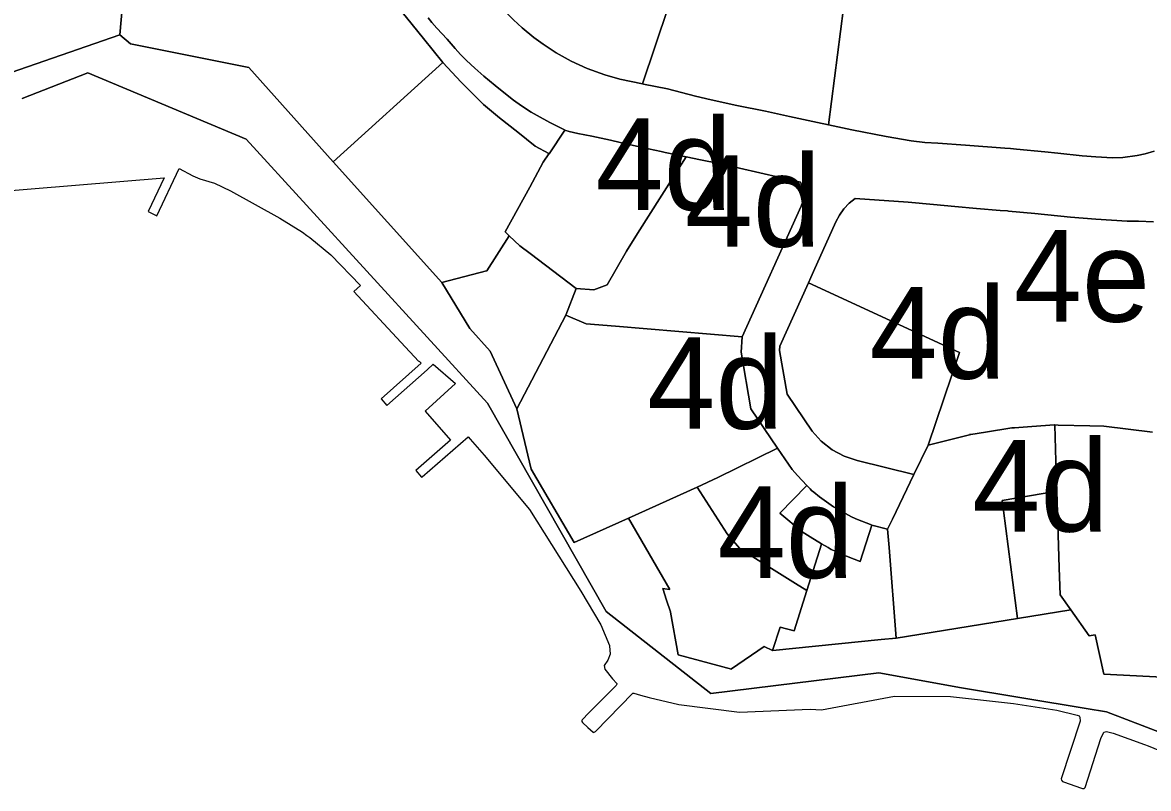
# Model space of a CAD drawing. Extents: x 598968 to 613553, y 4409678 to 4430833.
# Drawn here: x 608951 to 609098.4, y 4416657.6 to 4416758 of the extents above; entities that cross this region are included whole.
import ezdxf

# ---------------------------------------------------------------- set-up
doc = ezdxf.new("R2010")
doc.units = 0
for name, color, linetype in [('1', 7, 'Continuous'), ('4d. Sector de consolidació - ANNEX III A', 7, 'Continuous'), ('4e. Sector de consolidació - ANNEX III A', 7, 'Continuous')]:
    doc.layers.add(name, color=color, linetype=linetype)

msp = doc.modelspace()

# ---------------------------------------------------------------- linework, layer by layer
at = {"layer": '1'}
for points in [[(608987.0877, 4416776.1416), (609003.4782, 4416755.8932), (609006.0154, 4416752.7588), (609008.397, 4416750.1506), (609011.328, 4416747.2255), (609013.4226, 4416745.4815), (609015.8455, 4416743.5998), (609018.1041, 4416741.787), (609019.8769, 4416740.8037), (609019.9102, 4416740.7852), (609021.9971, 4416743.894), (609021.945, 4416743.9178), (609020.0295, 4416744.875), (609018.3446, 4416745.7945), (609017.5768, 4416746.2442), (609016.2868, 4416747.0752), (609015.2545, 4416747.8133), (609014.2052, 4416748.6265), (609012.8624, 4416749.7131), (609011.3621, 4416750.9714), (609010.1811, 4416752.0005), (609009.0988, 4416753.0034), (609008.3312, 4416753.7846), (609007.6371, 4416754.5791), (609006.5937, 4416755.7997), (609005.2224, 4416757.2264), (609004.5585, 4416757.9704), (609004.0997, 4416758.5969)], [(609060.0592, 4416772.136), (609056.5294, 4416744.5677), (609056.5287, 4416744.5623), (609059.5763, 4416743.9307), (609064.0504, 4416743.0457), (609067.3301, 4416742.4837), (609069.136, 4416742.2794), (609070.8092, 4416742.1551), (609074.4638, 4416741.8916), (609079.5883, 4416741.5384), (609080.3625, 4416741.4743), (609081.1235, 4416741.3972), (609084.8211, 4416741.0164), (609086.5239, 4416740.8418), (609089.7094, 4416740.5159), (609091.5331, 4416740.3631), (609093.6845, 4416740.2563), (609095.0525, 4416740.2923), (609096.9507, 4416740.5399), (609097.9963, 4416740.7699), (609099.1764, 4416741.1323)], [(609004.0997, 4416758.5969), (609004.5585, 4416757.9704), (609005.2224, 4416757.2264), (609006.5937, 4416755.7997), (609007.6371, 4416754.5791), (609008.3312, 4416753.7846), (609009.0988, 4416753.0034), (609010.1811, 4416752.0005), (609011.3621, 4416750.9714), (609012.8624, 4416749.7131), (609014.2052, 4416748.6265), (609015.2545, 4416747.8133), (609016.2868, 4416747.0752), (609017.5768, 4416746.2442), (609018.3446, 4416745.7945), (609020.0295, 4416744.875), (609021.945, 4416743.9178), (609021.9971, 4416743.894), (609022.5575, 4416743.6945), (609023.6832, 4416743.4548), (609025.525, 4416743.1017), (609027.9815, 4416742.5463), (609029.2108, 4416742.2692), (609032.9329, 4416741.4381), (609034.5963, 4416741.0709), (609035.101, 4416740.9643), (609037.87, 4416740.3973), (609039.7574, 4416740.0094), (609042.1979, 4416739.4918), (609052.8646, 4416737.0656), (609053.0938, 4416736.4551), (609053.2159, 4416735.8146), (609053.2272, 4416735.1627), (609053.1276, 4416734.5183), (609052.9198, 4416733.9002), (609045.2239, 4416716.8026), (609045.0867, 4416714.7828), (609046.3281, 4416707.381), (609049.8464, 4416702.2208), (609051.7312, 4416699.4396), (609052.4592, 4416698.6219), (609053.6779, 4416697.3359), (609054.0958, 4416696.8949), (609054.3043, 4416696.675), (609054.6107, 4416696.4424), (609055.3228, 4416695.8164), (609057.1475, 4416694.5167), (609059.506, 4416693.2163), (609059.6005, 4416693.1642), (609060.3276, 4416692.8771), (609062.006, 4416692.2144), (609062.206, 4416692.1354), (609064.2562, 4416691.5819), (609064.9022, 4416692.9286), (609067.6919, 4416698.7433), (609060.2533, 4416700.5877), (609058.5552, 4416701.1622), (609056.9792, 4416702.0165), (609055.5712, 4416703.1262), (609054.372, 4416704.4588), (609051.0777, 4416709.2906), (609050.1149, 4416715.0303), (609050.1515, 4416715.5686), (609053.8948, 4416723.885), (609054.2012, 4416724.5657), (609054.5515, 4416725.344), (609057.4791, 4416731.8482), (609057.9344, 4416732.7525), (609058.5173, 4416733.5805), (609059.2152, 4416734.3144), (609060.0129, 4416734.938), (609066.928, 4416734.4492), (609070.2692, 4416734.1299), (609073.0466, 4416733.8661), (609075.8834, 4416733.6256), (609078.9895, 4416733.373), (609079.9699, 4416733.2884), (609080.0752, 4416733.2796), (609083.5204, 4416732.9464), (609088.219, 4416732.48), (609091.5363, 4416732.214), (609095.633, 4416731.9749), (609097.0929, 4416731.9379), (609099.0532, 4416731.8883)], [(609099.1764, 4416741.1323), (609097.9963, 4416740.7699), (609096.9507, 4416740.5399), (609095.0525, 4416740.2923), (609093.6845, 4416740.2563), (609091.5331, 4416740.3631), (609089.7094, 4416740.5159), (609086.5239, 4416740.8418), (609084.8211, 4416741.0164), (609081.1235, 4416741.3972), (609080.3625, 4416741.4743), (609079.5883, 4416741.5384), (609074.4638, 4416741.8916), (609070.8092, 4416742.1551), (609069.136, 4416742.2794), (609067.3301, 4416742.4837), (609064.0504, 4416743.0457), (609059.5763, 4416743.9307), (609056.5287, 4416744.5623), (609055.079, 4416744.8708), (609051.3947, 4416745.6653), (609048.2395, 4416746.3451), (609044.5273, 4416747.1241), (609041.1325, 4416747.838), (609039.0863, 4416748.3369), (609035.4392, 4416749.2726), (609032.2943, 4416749.9113), (609032.1364, 4416749.9379), (609029.1931, 4416750.5426), (609027.1985, 4416751.1124), (609024.9086, 4416751.9602), (609022.7972, 4416752.9261), (609020.8487, 4416754.0143), (609019.125, 4416755.1325), (609017.9389, 4416756.0081), (609016.413, 4416757.2806), (609015.2628, 4416758.3509)], [(609100.2514, 4416672.2155), (609092.5832, 4416672.5994), (609091.4176, 4416677.7434), (609090.6308, 4416677.6353), (609088.2429, 4416681.0208), (609081.2483, 4416679.8886), (609065.3862, 4416677.3213), (609063.4291, 4416677.1277), (609049.1998, 4416675.7197), (609049.1955, 4416675.7212), (609048.0996, 4416676.2155), (609043.7951, 4416673.2812), (609043.7927, 4416673.2795), (609036.8413, 4416675.148), (609035.8312, 4416680.7472), (609035.8296, 4416680.7529), (609035.3159, 4416682.312), (609034.8144, 4416683.8355), (609035.0867, 4416683.8029), (609035.7392, 4416683.6936), (609030.298, 4416693.0468), (609023.2232, 4416689.845), (609017.5907, 4416699.45), (609015.7009, 4416707.372), (609012.182, 4416714.9272), (609009.5399, 4416717.894), (609005.856, 4416723.919), (609005.8631, 4416723.9218), (608991.6521, 4416739.7249), (608980.5997, 4416752.0903), (608965.091, 4416755.1885), (608963.7088, 4416756.3476), (608948.3247, 4416751.0557)], [(608950.9096, 4416748.0147), (608959.5132, 4416751.3932), (608980.2407, 4416742.6806), (609011.8707, 4416708.1096), (609027.3949, 4416680.8073), (609041.0946, 4416670.0876), (609063.0829, 4416672.7865), (609066.7132, 4416672.1246), (609073.6662, 4416670.8568), (609073.6719, 4416670.8559), (609090.2482, 4416668.1064), (609092.9199, 4416667.6633), (609117.6195, 4416658.1771)], [(609117.6195, 4416658.1771), (609092.9199, 4416667.6633), (609090.2482, 4416668.1064), (609073.6719, 4416670.8559), (609073.6662, 4416670.8568), (609066.7132, 4416672.1246), (609063.0829, 4416672.7865), (609041.0946, 4416670.0876), (609027.3949, 4416680.8073), (609011.8707, 4416708.1096), (608980.2407, 4416742.6806), (608959.5132, 4416751.3932), (608950.9096, 4416748.0147)], [(608946.2527, 4416735.7078), (608969.4922, 4416737.6286), (608967.4022, 4416733.2086), (608967.7454, 4416733.0473), (608968.5722, 4416732.6586), (608971.4921, 4416738.8386), (608973.2618, 4416737.9081), (608974.192, 4416737.4987), (608976.122, 4416736.9188), (608978.202, 4416735.9289), (608984.6718, 4416732.3292), (608987.6318, 4416730.4994), (608988.2052, 4416730.0932), (608988.5918, 4416729.8194), (608991.3318, 4416727.5396), (608995.2216, 4416723.5298), (608994.3517, 4416722.7198), (609000.5123, 4416716.0811), (609002.8516, 4416713.5604), (609002.925, 4416713.6247), (609003.1808, 4416713.3492), (608997.9079, 4416708.6911), (608998.6739, 4416707.8231), (609003.9468, 4416712.4812), (609004.7272, 4416713.2172), (609007.6714, 4416710.6906), (609003.6916, 4416707.0506), (609007.0015, 4416703.2408), (609002.4616, 4416699.2907), (609003.2316, 4416698.4008), (609003.3151, 4416698.4731), (609009.3414, 4416703.6908), (609009.5843, 4416703.4118), (609011.4214, 4416701.301), (609017.3414, 4416694.1614), (609024.0912, 4416683.4718), (609026.6912, 4416679.0521), (609027.8116, 4416676.3789), (609027.8312, 4416676.3322), (609027.9212, 4416675.2022), (609027.6012, 4416674.4222), (609027.1412, 4416673.7222), (609027.2312, 4416673.2522), (609028.2312, 4416672.0023), (609028.8012, 4416671.3624), (609028.7912, 4416671.2924), (609028.7612, 4416671.2224), (609028.7012, 4416671.1024), (609025.9213, 4416668.3423), (609025.7726, 4416668.1892), (609025.1286, 4416667.5258), (609024.2514, 4416666.6223), (609024.2114, 4416666.5123), (609024.2114, 4416666.4123), (609024.3114, 4416666.2623), (609025.0033, 4416665.6314), (609025.6713, 4416665.0224), (609025.7713, 4416664.9824), (609025.8083, 4416664.9994), (609026.0113, 4416665.0924), (609030.9012, 4416670.0924), (609031.0212, 4416670.1324), (609031.8712, 4416669.8625), (609033.0311, 4416669.5326), (609036.921, 4416668.6127), (609044.8708, 4416667.613), (609054.0906, 4416668.0133), (609055.6006, 4416667.9434), (609065.1504, 4416669.7236), (609065.1607, 4416669.7235), (609072.4702, 4416669.6639), (609080.75, 4416668.7442), (609086.3999, 4416667.8844), (609089.0898, 4416667.2446), (609089.3298, 4416667.1246), (609089.3714, 4416667.0552), (609089.4198, 4416666.9746), (609089.4201, 4416666.9686), (609089.4498, 4416666.4446), (609086.99, 4416658.8947), (609087.02, 4416658.7247), (609087.17, 4416658.5547), (609087.4371, 4416658.4565), (609089.5099, 4416657.6948), (609089.7899, 4416657.6248), (609090.0099, 4416657.6448), (609090.1099, 4416657.7648), (609092.1698, 4416664.1547), (609092.5598, 4416665.0047), (609092.8998, 4416665.0847), (609093.8098, 4416664.8848), (609097.8897, 4416663.405), (609098.3796, 4416663.235), (609104.0996, 4416660.8352)]]:
    msp.add_lwpolyline(points, dxfattribs=at)
for points in [[(609019.9102, 4416740.7852), (609019.8769, 4416740.8037), (609018.1041, 4416741.787), (609015.8455, 4416743.5998), (609013.4226, 4416745.4815), (609011.328, 4416747.2255), (609008.397, 4416750.1506), (609006.0154, 4416752.7588), (608991.6521, 4416739.7249), (609005.8631, 4416723.9218), (609011.7447, 4416725.4549), (609011.7518, 4416725.4574), (609014.6929, 4416730.0384), (609014.6968, 4416730.0445), (609014.1486, 4416730.5608), (609017.3955, 4416736.4272), (609019.1395, 4416739.6686), (609019.8997, 4416740.7696)], [(609023.4587, 4416723.143), (609017.4252, 4416727.7126), (609016.0943, 4416728.7286), (609014.6968, 4416730.0445), (609014.6929, 4416730.0384), (609011.7518, 4416725.4574), (609011.7447, 4416725.4549), (609005.8631, 4416723.9218), (609005.856, 4416723.919), (609009.5399, 4416717.894), (609012.182, 4416714.9272), (609015.7009, 4416707.372), (609022.1296, 4416719.6574)], [(609053.6779, 4416697.3359), (609052.4592, 4416698.6219), (609051.7312, 4416699.4396), (609049.8464, 4416702.2208), (609049.8394, 4416702.2176), (609042.0379, 4416698.3597), (609039.3057, 4416697.1233), (609043.2608, 4416691.0109), (609044.852, 4416689.1018), (609044.8662, 4416689.0849), (609052.1805, 4416684.466), (609053.6866, 4416683.5509), (609055.6006, 4416689.6141), (609055.5931, 4416689.6191), (609055.615, 4416689.6889), (609054.0936, 4416690.605), (609053.0784, 4416691.2725), (609050.1529, 4416693.7137), (609053.6396, 4416697.296)], [(609062.206, 4416692.1354), (609062.006, 4416692.2144), (609060.3276, 4416692.8771), (609059.6005, 4416693.1642), (609059.506, 4416693.2163), (609057.1475, 4416694.5167), (609055.3228, 4416695.8164), (609054.6107, 4416696.4424), (609054.3043, 4416696.675), (609054.0958, 4416696.8949), (609053.6779, 4416697.3359), (609053.6396, 4416697.296), (609050.1529, 4416693.7137), (609053.0784, 4416691.2725), (609054.0936, 4416690.605), (609055.615, 4416689.6889), (609056.4481, 4416689.1872), (609056.8541, 4416688.9426), (609057.2785, 4416688.7688), (609058.0784, 4416688.3658), (609060.6716, 4416687.3791)], [(609088.2429, 4416681.0208), (609086.8528, 4416682.9918), (609086.7377, 4416686.5234), (609086.4559, 4416695.1751), (609086.4104, 4416696.5719), (609079.2721, 4416695.3628), (609079.4411, 4416694.0397), (609081.2483, 4416679.8886)], [(609064.2562, 4416691.5819), (609062.206, 4416692.1354), (609060.6716, 4416687.3791), (609058.0784, 4416688.3658), (609057.2785, 4416688.7688), (609056.8541, 4416688.9426), (609056.4481, 4416689.1872), (609055.615, 4416689.6889), (609055.5931, 4416689.6191), (609055.6006, 4416689.6141), (609053.6866, 4416683.5509), (609052.026, 4416678.285), (609050.1779, 4416678.7771), (609049.1955, 4416675.7212), (609049.1998, 4416675.7197), (609063.4291, 4416677.1277), (609065.3862, 4416677.3213), (609064.4434, 4416689.2195)]]:
    msp.add_lwpolyline(points, close=True, dxfattribs=at)
at = {"layer": '4d. Sector de consolidació - ANNEX III A'}
for points in [[(608987.0877, 4416776.1416), (608984.8795, 4416773.9754), (608984.5578, 4416773.5427), (608983.1833, 4416766.0925), (608977.0655, 4416780.8764), (608968.086, 4416781.6902), (608968.1193, 4416782.0347), (608965.8758, 4416780.8999), (608963.7088, 4416756.3476), (608965.091, 4416755.1885), (608980.5997, 4416752.0903), (608991.6521, 4416739.7249), (609006.0154, 4416752.7588), (609003.4782, 4416755.8932)], [(608965.8758, 4416780.8999), (608963.787, 4416781.2229), (608959.629, 4416779.6886), (608959.4125, 4416780.7447), (608957.0885, 4416779.8692), (608940.5871, 4416773.6525), (608946.9199, 4416755.6304), (608948.3247, 4416751.0557), (608963.7088, 4416756.3476)], [(609037.87, 4416740.3973), (609035.101, 4416740.9643), (609034.5963, 4416741.0709), (609032.9329, 4416741.4381), (609029.2108, 4416742.2692), (609027.9815, 4416742.5463), (609025.525, 4416743.1017), (609023.6832, 4416743.4548), (609022.5575, 4416743.6945), (609021.9971, 4416743.894), (609019.9102, 4416740.7852), (609019.8997, 4416740.7696), (609019.1395, 4416739.6686), (609017.3955, 4416736.4272), (609014.1486, 4416730.5608), (609014.6968, 4416730.0445), (609016.0943, 4416728.7286), (609017.4252, 4416727.7126), (609023.4587, 4416723.143), (609025.7889, 4416722.9388), (609027.5441, 4416723.6222), (609030.0406, 4416728.0093), (609031.5169, 4416730.3452)], [(609045.2239, 4416716.8026), (609052.9198, 4416733.9002), (609053.1276, 4416734.5183), (609053.2272, 4416735.1627), (609053.2159, 4416735.8146), (609053.0938, 4416736.4551), (609052.8646, 4416737.0656), (609042.1979, 4416739.4918), (609039.7574, 4416740.0094), (609037.87, 4416740.3973), (609031.5169, 4416730.3452), (609030.0406, 4416728.0093), (609027.5441, 4416723.6222), (609025.7889, 4416722.9388), (609023.4587, 4416723.143), (609022.1296, 4416719.6574), (609024.7887, 4416718.5155), (609028.6217, 4416718.1941)], [(609069.5505, 4416702.6172), (609073.666, 4416714.732), (609053.8948, 4416723.885), (609050.1515, 4416715.5686), (609050.1149, 4416715.0303), (609051.0777, 4416709.2906), (609054.372, 4416704.4588), (609055.5712, 4416703.1262), (609056.9792, 4416702.0165), (609058.5552, 4416701.1622), (609060.2533, 4416700.5877), (609067.6919, 4416698.7433)], [(609045.2239, 4416716.8026), (609028.6217, 4416718.1941), (609024.7887, 4416718.5155), (609022.1296, 4416719.6574), (609015.7009, 4416707.372), (609017.5907, 4416699.45), (609023.2232, 4416689.845), (609030.298, 4416693.0468), (609039.3057, 4416697.1233), (609042.0379, 4416698.3597), (609049.8394, 4416702.2176), (609049.8464, 4416702.2208), (609046.3281, 4416707.381), (609045.0867, 4416714.7828)], [(609086.4104, 4416696.5719), (609086.2821, 4416700.5095), (609086.1286, 4416705.2189), (609086.1274, 4416705.2565), (609083.1597, 4416705.0492), (609080.8679, 4416704.8888), (609080.5313, 4416704.8649), (609080.5214, 4416704.8638), (609077.0568, 4416704.3119), (609075.1568, 4416704.0094), (609074.9914, 4416703.9829), (609074.9862, 4416703.9818), (609069.5505, 4416702.6172), (609067.6919, 4416698.7433), (609064.9022, 4416692.9286), (609064.2562, 4416691.5819), (609064.4434, 4416689.2195), (609065.3862, 4416677.3213), (609081.2483, 4416679.8886), (609079.4411, 4416694.0397), (609079.2721, 4416695.3628)], [(609053.6866, 4416683.5509), (609052.1805, 4416684.466), (609044.8662, 4416689.0849), (609044.852, 4416689.1018), (609043.2608, 4416691.0109), (609039.3057, 4416697.1233), (609030.298, 4416693.0468), (609035.7392, 4416683.6936), (609035.0867, 4416683.8029), (609034.8144, 4416683.8355), (609035.3159, 4416682.312), (609035.8296, 4416680.7529), (609035.8312, 4416680.7472), (609036.8413, 4416675.148), (609043.7927, 4416673.2795), (609043.7951, 4416673.2812), (609048.0996, 4416676.2155), (609049.1955, 4416675.7212), (609050.1779, 4416678.7771), (609052.026, 4416678.285)]]:
    msp.add_lwpolyline(points, close=True, dxfattribs=at)
msp.add_lwpolyline([(609098.9225, 4416704.2958), (609092.5492, 4416705.0989), (609090.7351, 4416705.1437), (609086.5932, 4416705.2454), (609086.137, 4416705.2567), (609086.1274, 4416705.2565), (609086.1286, 4416705.2189), (609086.2821, 4416700.5095), (609086.4104, 4416696.5719), (609086.4559, 4416695.1751), (609086.7377, 4416686.5234), (609086.8528, 4416682.9918), (609088.2429, 4416681.0208), (609090.6308, 4416677.6353), (609091.4176, 4416677.7434), (609092.5832, 4416672.5994), (609100.2514, 4416672.2155)], dxfattribs=at)
at = {"layer": '4e. Sector de consolidació - ANNEX III A'}
for points in [[(609044.0001, 4416785.1913), (609032.4908, 4416794.5479), (609012.0552, 4416761.7083), (609013.6947, 4416759.9466), (609015.2628, 4416758.3509), (609016.413, 4416757.2806), (609017.9389, 4416756.0081), (609019.125, 4416755.1325), (609020.8487, 4416754.0143), (609022.7972, 4416752.9261), (609024.9086, 4416751.9602), (609027.1985, 4416751.1124), (609029.1931, 4416750.5426), (609032.1364, 4416749.9379)], [(609056.5287, 4416744.5623), (609056.5294, 4416744.5677), (609060.0592, 4416772.136), (609044.0001, 4416785.1913), (609032.1364, 4416749.9379), (609032.2943, 4416749.9113), (609035.4392, 4416749.2726), (609039.0863, 4416748.3369), (609041.1325, 4416747.838), (609044.5273, 4416747.1241), (609048.2395, 4416746.3451), (609051.3947, 4416745.6653), (609055.079, 4416744.8708)]]:
    msp.add_lwpolyline(points, close=True, dxfattribs=at)
msp.add_lwpolyline([(609099.0532, 4416731.8883), (609097.0929, 4416731.9379), (609095.633, 4416731.9749), (609091.5363, 4416732.214), (609088.219, 4416732.48), (609083.5204, 4416732.9464), (609080.0752, 4416733.2796), (609079.9699, 4416733.2884), (609078.9895, 4416733.373), (609075.8834, 4416733.6256), (609073.0466, 4416733.8661), (609070.2692, 4416734.1299), (609066.928, 4416734.4492), (609060.0129, 4416734.938), (609059.2152, 4416734.3144), (609058.5173, 4416733.5805), (609057.9344, 4416732.7525), (609057.4791, 4416731.8482), (609054.5515, 4416725.344), (609054.2012, 4416724.5657), (609053.8948, 4416723.885), (609073.666, 4416714.732), (609069.5505, 4416702.6172), (609074.9862, 4416703.9818), (609074.9914, 4416703.9829), (609075.1568, 4416704.0094), (609077.0568, 4416704.3119), (609080.5214, 4416704.8638), (609080.5313, 4416704.8649), (609080.8679, 4416704.8888), (609083.1597, 4416705.0492), (609086.1274, 4416705.2565), (609086.137, 4416705.2567), (609086.5932, 4416705.2454), (609090.7351, 4416705.1437), (609092.5492, 4416705.0989), (609098.9225, 4416704.2958)], dxfattribs=at)

# ---------------------------------------------------------------- texts
at = {"layer": '4d. Sector de consolidació - ANNEX III A'}
for p in [(609026.0093, 4416733.4164), (609037.6784, 4416728.5999), (609061.8905, 4416711.3141), (609032.7736, 4416704.7512), (609075.3333, 4416691.2889), (609041.9923, 4416685.2014)]:
    msp.add_text('4d', height=12, dxfattribs=at).set_placement(p)
at = {"layer": '4e. Sector de consolidació - ANNEX III A'}
msp.add_text('4e', height=12, dxfattribs=at).set_placement((609080.7698, 4416718.7776))

doc.saveas('drawing.dxf')
